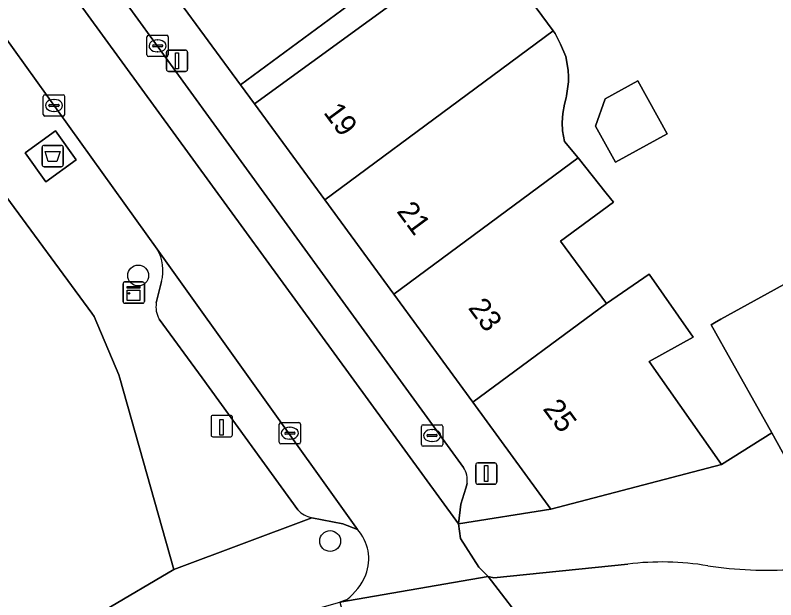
# Model space of a CAD drawing. Extents: x 161798 to 162385, y 382315 to 382833.
# Drawn here: x 162012.08 to 162047.7, y 382382.05 to 382409.46 of the extents above; entities that cross this region are included whole.
import ezdxf

# ---------------------------------------------------------------- set-up
doc = ezdxf.new("R2010")
doc.units = 0
for name, color, linetype in [('IMGEO_Afval_apart_plaats', 7, 'Continuous'), ('IMGEO_Boom', 7, 'Continuous'), ('IMGEO_Erf', 7, 'Continuous'), ('IMGEO_Fietspad_open', 7, 'Continuous'), ('IMGEO_Kast', 7, 'Continuous'), ('IMGEO_Kolk', 7, 'Continuous'), ('IMGEO_Laadpaal', 7, 'Continuous'), ('IMGEO_Lichtmast', 7, 'Continuous'), ('IMGEO_Pand', 7, 'Continuous'), ('IMGEO_Pand_nummerreeks', 7, 'Continuous'), ('IMGEO_Parkeervlak_open', 7, 'Continuous'), ('IMGEO_Rijbaan_lokaal_gesloten', 7, 'Continuous'), ('IMGEO_Rijbaan_lokaal_open', 7, 'Continuous'), ('IMGEO_Voetpad_gesloten', 7, 'Continuous'), ('IMGEO_Voetpad_open', 7, 'Continuous')]:
    doc.layers.add(name, color=color, linetype=linetype)

msp = doc.modelspace()

# ---------------------------------------------------------------- linework, layer by layer
at = {"layer": 'IMGEO_Afval_apart_plaats'}
for p, q in [((162013.335, 382402.456), (162013.335, 382403.256)), ((162013.335, 382403.256), (162013.335, 382402.456)), ((162013.435, 382403.356), (162014.225, 382403.356)), ((162014.225, 382403.356), (162013.435, 382403.356)), ((162014.325, 382403.256), (162014.325, 382402.456)), ((162014.325, 382402.456), (162014.325, 382403.256)), ((162014.225, 382402.356), (162013.435, 382402.356)), ((162013.435, 382402.356), (162014.225, 382402.356))]:
    msp.add_line(p, q, dxfattribs=at)
msp.add_lwpolyline([(162013.478, 382403.07), (162014.182, 382403.07), (162014.033, 382402.6), (162013.627, 382402.6), (162013.478, 382403.07)], dxfattribs=at)
for centre, start, end in [((162013.435, 382403.256), 90, 180), ((162013.435, 382403.256), 90, 180), ((162014.225, 382403.256), 0, 90), ((162014.225, 382403.256), 360, 90), ((162013.435, 382402.456), 180, 270), ((162013.435, 382402.456), 180, 270), ((162014.225, 382402.456), 270, 0), ((162014.225, 382402.456), 270, 0)]:
    msp.add_arc(centre, 0.1, start, end, dxfattribs=at)
at = {"layer": 'IMGEO_Boom'}
for centre in [(162017.836, 382397.254), (162026.826, 382384.808)]:
    msp.add_circle(centre, 0.489, dxfattribs=at)
at = {"layer": 'IMGEO_Erf'}
for points in [[(162033.311, 382414.087), (162022.628, 382406.187), (162023.288, 382405.3), (162034.023, 382413.125)], [(162035.94, 382410.533), (162037.275, 382408.724), (162037.365, 382408.601), (162037.619, 382408.106), (162037.863, 382407.521), (162037.979, 382406.887), (162037.982, 382406.573), (162037.984, 382406.331), (162037.894, 382405.679), (162037.872, 382405.582), (162037.802, 382405.282), (162037.726, 382404.852), (162037.698, 382404.423), (162037.701, 382404.042), (162037.801, 382403.535), (162038.444, 382402.777), (162039.754, 382401.12), (162040.089, 382400.696), (162037.607, 382398.861), (162039.763, 382395.945), (162041.759, 382397.315), (162043.834, 382394.36), (162041.77, 382393.217), (162045.159, 382388.391), (162047.51, 382389.884), (162045.251, 382393.911), (162045.115, 382394.154), (162044.67, 382394.948), (162044.823, 382395.032), (162045.13, 382395.203), (162050.256, 382398.043)]]:
    msp.add_lwpolyline(points, dxfattribs=at)
msp.add_lwpolyline([(162042.606, 382403.901), (162040.188, 382402.561), (162039.252, 382404.249), (162039.712, 382405.536), (162041.233, 382406.379)], close=True, dxfattribs=at)
at = {"layer": 'IMGEO_Fietspad_open'}
msp.add_lwpolyline([(162040.773, 382383.73), (162034.494, 382383.089), (162034.232, 382383.139), (162036.149, 382380.646), (162036.87, 382379.709)], dxfattribs=at)
for centre, radius, start, end in [((162042.359, 382370.687), 13.139, 80.5822, 96.9337), ((162047.361, 382402.946), 19.506, 261.594, 273.4107)]:
    msp.add_arc(centre, radius, start, end, dxfattribs=at)
at = {"layer": 'IMGEO_Kast'}
for p, q in [((162017.125, 382396.028), (162017.125, 382396.869)), ((162017.125, 382396.869), (162017.125, 382396.028)), ((162017.2, 382396.953), (162018.041, 382396.953)), ((162018.041, 382396.953), (162017.2, 382396.953)), ((162018.125, 382396.878), (162018.125, 382396.037)), ((162018.125, 382396.037), (162018.125, 382396.878)), ((162018.05, 382395.953), (162017.209, 382395.953)), ((162017.209, 382395.953), (162018.05, 382395.953))]:
    msp.add_line(p, q, dxfattribs=at)
for points in [[(162017.32, 382396.743), (162017.92, 382396.743), (162017.92, 382396.658), (162017.32, 382396.658), (162017.32, 382396.743)], [(162017.32, 382396.568), (162017.92, 382396.568), (162017.92, 382396.079), (162017.32, 382396.079), (162017.32, 382396.568)]]:
    msp.add_lwpolyline(points, dxfattribs=at)
msp.add_circle((162017.404, 382396.417), 0.0377, dxfattribs=at)
for centre, start, end in [((162017.203, 382396.875), 92.4484, 184.2845), ((162017.203, 382396.875), 92.4484, 184.2845), ((162018.047, 382396.875), 2.4484, 94.2845), ((162018.047, 382396.875), 2.4484, 94.2845), ((162017.203, 382396.031), 182.4484, 274.2845), ((162017.203, 382396.031), 182.4484, 274.2845), ((162018.047, 382396.031), 272.4484, 4.2845), ((162018.047, 382396.031), 272.4484, 4.2845)]:
    msp.add_arc(centre, 0.0779, start, end, dxfattribs=at)
at = {"layer": 'IMGEO_Kolk'}
for p, q in [((162018.245, 382407.593), (162018.245, 382408.445)), ((162018.32, 382408.519), (162019.172, 382408.519)), ((162018.733, 382408.299), (162018.758, 382408.299)), ((162019.246, 382408.445), (162019.246, 382407.593)), ((162018.504, 382408.013), (162018.504, 382408.025)), ((162018.942, 382407.976), (162018.544, 382407.976)), ((162018.547, 382408.062), (162018.945, 382408.062)), ((162018.988, 382408.025), (162018.988, 382408.013)), ((162018.756, 382407.739), (162018.731, 382407.739)), ((162019.172, 382407.519), (162018.32, 382407.519)), ((162013.391, 382404.8), (162013.391, 382405.652)), ((162013.466, 382405.726), (162014.318, 382405.726)), ((162013.879, 382405.506), (162013.904, 382405.506)), ((162014.392, 382405.652), (162014.392, 382404.8)), ((162013.65, 382405.22), (162013.65, 382405.232)), ((162014.088, 382405.183), (162013.69, 382405.183)), ((162013.693, 382405.269), (162014.091, 382405.269)), ((162014.134, 382405.232), (162014.134, 382405.22)), ((162014.318, 382404.726), (162013.466, 382404.726)), ((162013.902, 382404.946), (162013.877, 382404.946)), ((162024.439, 382389.437), (162024.439, 382390.289)), ((162024.514, 382390.363), (162025.366, 382390.363)), ((162024.927, 382390.143), (162024.952, 382390.143)), ((162025.44, 382390.289), (162025.44, 382389.437)), ((162031.1, 382389.329), (162031.1, 382390.181)), ((162031.175, 382390.255), (162032.027, 382390.255)), ((162032.101, 382390.181), (162032.101, 382389.329)), ((162024.698, 382389.857), (162024.698, 382389.869)), ((162025.136, 382389.82), (162024.738, 382389.82)), ((162024.741, 382389.906), (162025.139, 382389.906)), ((162025.182, 382389.869), (162025.182, 382389.857)), ((162031.359, 382389.749), (162031.359, 382389.761)), ((162031.402, 382389.798), (162031.8, 382389.798)), ((162031.588, 382390.035), (162031.613, 382390.035)), ((162031.843, 382389.761), (162031.843, 382389.749)), ((162025.366, 382389.363), (162024.514, 382389.363)), ((162024.95, 382389.583), (162024.925, 382389.583)), ((162031.797, 382389.712), (162031.399, 382389.712)), ((162031.611, 382389.475), (162031.586, 382389.475)), ((162032.027, 382389.255), (162031.175, 382389.255))]:
    msp.add_line(p, q, dxfattribs=at)
for points in [[(162018.245, 382407.593), (162018.245, 382408.445)], [(162018.32, 382408.519), (162019.172, 382408.519)], [(162019.246, 382408.445), (162019.246, 382407.593)], [(162019.172, 382407.519), (162018.32, 382407.519)], [(162013.391, 382404.8), (162013.391, 382405.652)], [(162013.466, 382405.726), (162014.318, 382405.726)], [(162014.392, 382405.652), (162014.392, 382404.8)], [(162014.318, 382404.726), (162013.466, 382404.726)], [(162024.439, 382389.437), (162024.439, 382390.289)], [(162024.514, 382390.363), (162025.366, 382390.363)], [(162025.44, 382390.289), (162025.44, 382389.437)], [(162031.1, 382389.329), (162031.1, 382390.181)], [(162031.175, 382390.255), (162032.027, 382390.255)], [(162032.101, 382390.181), (162032.101, 382389.329)], [(162025.366, 382389.363), (162024.514, 382389.363)], [(162032.027, 382389.255), (162031.175, 382389.255)]]:
    msp.add_lwpolyline(points, dxfattribs=at)
for centre, radius, start, end in [((162018.322, 382408.443), 0.0765, 91.552, 178.448), ((162018.322, 382408.443), 0.0765, 91.552, 178.448), ((162019.17, 382408.443), 0.0765, 1.552, 88.448), ((162019.17, 382408.443), 0.0765, 1.552, 88.448), ((162018.544, 382408.022), 0.0403, 85.8775, 175.7526), ((162018.541, 382408.012), 0.0366, 178.938, 274.7102), ((162018.945, 382408.019), 0.043, 264.8664, 352.4533), ((162018.949, 382408.024), 0.0386, 1.7309, 96.639), ((162018.322, 382407.595), 0.0765, 181.552, 268.448), ((162018.322, 382407.595), 0.0765, 181.552, 268.448), ((162019.17, 382407.595), 0.0765, 271.552, 358.448), ((162019.17, 382407.595), 0.0765, 271.552, 358.448), ((162013.468, 382405.65), 0.0765, 91.552, 178.448), ((162013.468, 382405.65), 0.0765, 91.552, 178.448), ((162014.316, 382405.65), 0.0765, 1.552, 88.448), ((162014.316, 382405.65), 0.0765, 1.552, 88.448), ((162013.69, 382405.229), 0.0403, 85.8775, 175.7526), ((162013.687, 382405.219), 0.0366, 178.938, 274.7102), ((162014.091, 382405.226), 0.043, 264.8664, 352.4533), ((162014.095, 382405.231), 0.0386, 1.7309, 96.639), ((162013.468, 382404.802), 0.0765, 181.552, 268.448), ((162013.468, 382404.802), 0.0765, 181.552, 268.448), ((162014.316, 382404.802), 0.0765, 271.552, 358.448), ((162014.316, 382404.802), 0.0765, 271.552, 358.448), ((162024.516, 382390.287), 0.0765, 91.552, 178.448), ((162024.516, 382390.287), 0.0765, 91.552, 178.448), ((162025.364, 382390.287), 0.0765, 1.552, 88.448), ((162025.364, 382390.287), 0.0765, 1.552, 88.448), ((162031.177, 382390.179), 0.0765, 91.552, 178.448), ((162031.177, 382390.179), 0.0765, 91.552, 178.448), ((162032.025, 382390.179), 0.0765, 1.552, 88.448), ((162032.025, 382390.179), 0.0765, 1.552, 88.448), ((162024.738, 382389.866), 0.0403, 85.8775, 175.7526), ((162024.735, 382389.856), 0.0366, 178.938, 274.7102), ((162025.139, 382389.863), 0.043, 264.8664, 352.4533), ((162025.143, 382389.868), 0.0386, 1.7309, 96.639), ((162031.399, 382389.758), 0.0403, 85.8775, 175.7526), ((162031.396, 382389.748), 0.0366, 178.938, 274.7102), ((162031.8, 382389.755), 0.043, 264.8664, 352.4533), ((162031.804, 382389.76), 0.0386, 1.7309, 96.639), ((162024.516, 382389.439), 0.0765, 181.552, 268.448), ((162024.516, 382389.439), 0.0765, 181.552, 268.448), ((162025.364, 382389.439), 0.0765, 271.552, 358.448), ((162025.364, 382389.439), 0.0765, 271.552, 358.448), ((162031.177, 382389.331), 0.0765, 181.552, 268.448), ((162031.177, 382389.331), 0.0765, 181.552, 268.448), ((162032.025, 382389.331), 0.0765, 271.552, 358.448), ((162032.025, 382389.331), 0.0765, 271.552, 358.448)]:
    msp.add_arc(centre, radius, start, end, dxfattribs=at)
for centre, major_axis, ratio, start_param, end_param in [((162018.732, 382408.019), (-0.387, 0.002), 0.722429, 4.712389, 7.853982), ((162018.757, 382408.019), (-0.39, 0.002), 0.717154, 1.570796, 4.712389), ((162013.878, 382405.226), (-0.387, 0.002), 0.722429, 4.712389, 7.853982), ((162013.903, 382405.226), (-0.39, 0.002), 0.717154, 1.570796, 4.712389), ((162024.926, 382389.863), (-0.387, 0.002), 0.722429, 4.712389, 7.853982), ((162024.951, 382389.863), (-0.39, 0.002), 0.717154, 1.570796, 4.712389), ((162031.587, 382389.755), (-0.387, 0.002), 0.722429, 4.712389, 7.853982), ((162031.612, 382389.755), (-0.39, 0.002), 0.717154, 1.570796, 4.712389)]:
    msp.add_ellipse(centre, major_axis=major_axis, ratio=ratio, start_param=start_param, end_param=end_param, dxfattribs=at)
at = {"layer": 'IMGEO_Laadpaal'}
for p, q in [((162021.248, 382390.614), (162021.248, 382389.773)), ((162021.248, 382390.614), (162021.248, 382389.773)), ((162022.164, 382390.698), (162021.323, 382390.698)), ((162022.164, 382390.698), (162021.323, 382390.698)), ((162022.248, 382389.782), (162022.248, 382390.623)), ((162022.248, 382389.782), (162022.248, 382390.623)), ((162021.332, 382389.698), (162022.173, 382389.698)), ((162021.332, 382389.698), (162022.173, 382389.698))]:
    msp.add_line(p, q, dxfattribs=at)
msp.add_lwpolyline([(162021.663, 382390.511), (162021.823, 382390.511), (162021.823, 382389.778), (162021.663, 382389.778), (162021.663, 382390.511)], dxfattribs=at)
for centre, start, end in [((162021.326, 382390.62), 92.4484, 184.2845), ((162021.326, 382390.62), 92.4484, 184.2845), ((162022.17, 382390.62), 2.4484, 94.2845), ((162022.17, 382390.62), 2.4484, 94.2845), ((162021.326, 382389.776), 182.4484, 274.2845), ((162021.326, 382389.776), 182.4484, 274.2845), ((162022.17, 382389.776), 272.4484, 4.2845), ((162022.17, 382389.776), 272.4484, 4.2845)]:
    msp.add_arc(centre, 0.0779, start, end, dxfattribs=at)
at = {"layer": 'IMGEO_Lichtmast'}
for p, q in [((162019.158, 382406.92), (162019.158, 382407.72)), ((162019.158, 382407.72), (162019.158, 382406.92)), ((162019.258, 382407.82), (162020.048, 382407.82)), ((162020.048, 382407.82), (162019.258, 382407.82)), ((162020.148, 382407.72), (162020.148, 382406.92)), ((162020.148, 382406.92), (162020.148, 382407.72)), ((162020.048, 382406.82), (162019.258, 382406.82)), ((162019.258, 382406.82), (162020.048, 382406.82)), ((162033.641, 382387.569), (162033.641, 382388.369)), ((162033.641, 382388.369), (162033.641, 382387.569)), ((162033.741, 382388.469), (162034.531, 382388.469)), ((162034.531, 382388.469), (162033.741, 382388.469)), ((162034.631, 382388.369), (162034.631, 382387.569)), ((162034.631, 382387.569), (162034.631, 382388.369)), ((162034.531, 382387.469), (162033.741, 382387.469)), ((162033.741, 382387.469), (162034.531, 382387.469))]:
    msp.add_line(p, q, dxfattribs=at)
for points in [[(162019.578, 382407.695), (162019.728, 382407.695), (162019.728, 382406.945), (162019.578, 382406.945), (162019.578, 382407.695)], [(162034.061, 382388.344), (162034.211, 382388.344), (162034.211, 382387.594), (162034.061, 382387.594), (162034.061, 382388.344)]]:
    msp.add_lwpolyline(points, dxfattribs=at)
for centre, start, end in [((162019.258, 382407.72), 90, 180), ((162019.258, 382407.72), 90, 180), ((162020.048, 382407.72), 0, 90), ((162020.048, 382407.72), 360, 90), ((162019.258, 382406.92), 180, 270), ((162019.258, 382406.92), 180, 270), ((162020.048, 382406.92), 270, 0), ((162020.048, 382406.92), 270, 0), ((162033.741, 382388.369), 90, 180), ((162033.741, 382388.369), 90, 180), ((162034.531, 382388.369), 0, 90), ((162034.531, 382388.369), 360, 90), ((162033.741, 382387.569), 180, 270), ((162033.741, 382387.569), 180, 270), ((162034.531, 382387.569), 270, 0), ((162034.531, 382387.569), 270, 0)]:
    msp.add_arc(centre, 0.1, start, end, dxfattribs=at)
at = {"layer": 'IMGEO_Pand'}
for points in [[(162028.892, 382420.064), (162029.989, 382420.875), (162029.76, 382421.198), (162027.154, 382424.872), (162022.598, 382421.64), (162025.311, 382417.648), (162018.079, 382412.392), (162022.628, 382406.187), (162033.311, 382414.087)], [(162037.275, 382408.724), (162035.94, 382410.533), (162034.023, 382413.125), (162023.288, 382405.3), (162026.571, 382400.806), (162033.241, 382405.74)], [(162038.444, 382402.777), (162037.801, 382403.535), (162037.701, 382404.042), (162037.698, 382404.423), (162037.726, 382404.852), (162037.802, 382405.282), (162037.872, 382405.582), (162037.894, 382405.679), (162037.984, 382406.331), (162037.982, 382406.573), (162037.979, 382406.887), (162037.863, 382407.521), (162037.619, 382408.106), (162037.365, 382408.601), (162037.275, 382408.724), (162033.241, 382405.74), (162026.571, 382400.806), (162029.806, 382396.378)], [(162039.252, 382404.249), (162040.188, 382402.561), (162042.606, 382403.901), (162041.233, 382406.379), (162039.712, 382405.536)], [(162038.444, 382402.777), (162029.806, 382396.378), (162033.504, 382391.316), (162039.763, 382395.945), (162037.607, 382398.861), (162040.089, 382400.696), (162039.754, 382401.12)], [(161992.986, 382387.688), (161996.279, 382375.983), (162000, 382377.033), (162005.41, 382378.559), (162009.526, 382379.708), (162009.093, 382381.268), (162011.466, 382381.97), (162011.964, 382380.39), (162012.37, 382380.501), (162016.275, 382381.566), (162019.512, 382383.48), (162016.974, 382392.447), (162016.93, 382392.603), (162015.773, 382395.333), (162015.66, 382395.487), (162011.459, 382401.201), (162002.027, 382394.301)], [(162050.256, 382398.043), (162045.13, 382395.203), (162044.823, 382395.032), (162044.67, 382394.948), (162045.115, 382394.154), (162045.251, 382393.911), (162047.51, 382389.884), (162049.503, 382386.257), (162055.054, 382389.385), (162051.941, 382395.003), (162051.601, 382395.616), (162050.944, 382396.801), (162050.426, 382397.737)], [(162033.504, 382391.316), (162037.166, 382386.303), (162045.159, 382388.391), (162041.77, 382393.217), (162043.834, 382394.36), (162041.759, 382397.315), (162039.763, 382395.945)]]:
    msp.add_lwpolyline(points, close=True, dxfattribs=at)
at = {"layer": 'IMGEO_Parkeervlak_open'}
for points in [[(162013.778, 382411.818), (162032.83, 382385.614), (162032.951, 382386.532), (162033.178, 382387.292), (162033.24, 382387.513)], [(162033.065, 382388.261), (162027.294, 382396.215), (162016.872, 382410.591)], [(162025.97, 382385.896), (162027.424, 382385.612), (162028.106, 382385.351), (162018.806, 382398.381), (162018.719, 382398.49)], [(162018.925, 382396.969), (162018.685, 382395.969)], [(162018.82, 382395.215), (162020.829, 382392.465), (162025.317, 382386.264)]]:
    msp.add_lwpolyline(points, dxfattribs=at)
for centre, radius, start, end in [((162017.071, 382397.492), 1.927, 344.2377, 31.1884), ((162019.772, 382395.774), 1.104, 169.8534, 210.4485), ((162032.197, 382387.664), 1.053, 351.7844, 34.5514), ((162026.253, 382387.162), 1.297, 223.8037, 257.3892)]:
    msp.add_arc(centre, radius, start, end, dxfattribs=at)
at = {"layer": 'IMGEO_Rijbaan_lokaal_gesloten'}
msp.add_lwpolyline([(162034.232, 382383.139), (162027.279, 382381.946), (162028.075, 382379.021), (162028.34, 382379.074), (162036.149, 382380.646)], close=True, dxfattribs=at)
at = {"layer": 'IMGEO_Rijbaan_lokaal_open'}
for points in [[(162013.778, 382411.818), (162012.33, 382413.906), (162009.488, 382418.005), (162002.849, 382427.58), (161999.682, 382425.259), (162009.841, 382410.886), (162009.951, 382410.728), (162018.719, 382398.49), (162018.806, 382398.381), (162028.106, 382385.351)], [(162027.597, 382382.054), (162027.279, 382381.946), (162034.232, 382383.139), (162033.787, 382383.577), (162032.934, 382384.925), (162032.83, 382385.614), (162013.778, 382411.818)]]:
    msp.add_lwpolyline(points, dxfattribs=at)
for centre, radius, start, end in [((162026.578, 382383.974), 2.057, 338.5663, 42.0387), ((162025.835, 382384.333), 2.881, 307.7062, 337.3085)]:
    msp.add_arc(centre, radius, start, end, dxfattribs=at)
at = {"layer": 'IMGEO_Voetpad_gesloten'}
msp.add_lwpolyline([(162013.96, 382404.032), (162012.536, 382403.004), (162013.513, 382401.65), (162014.937, 382402.678)], close=True, dxfattribs=at)
at = {"layer": 'IMGEO_Voetpad_open'}
for points in [[(161938.715, 382497.147), (161939.523, 382495.623), (161943.046, 382494.363), (161946.327, 382489.811), (161950.356, 382484.334), (161950.42, 382484.381), (161954.726, 382478.543), (161983.404, 382439.272), (161998.059, 382419.476), (162001.282, 382415.062), (162005.738, 382408.96), (162006.916, 382407.381), (162011.459, 382401.201), (162015.66, 382395.487), (162015.773, 382395.333), (162016.93, 382392.603), (162016.974, 382392.447), (162019.512, 382383.48), (162025.97, 382385.896)], [(162033.24, 382387.513), (162033.178, 382387.292), (162032.951, 382386.532), (162032.83, 382385.614), (162037.166, 382386.303), (162033.504, 382391.316), (162029.806, 382396.378), (162026.571, 382400.806), (162023.288, 382405.3), (162022.628, 382406.187), (162018.079, 382412.392), (162015.189, 382416.324), (162012.934, 382419.392), (161994.413, 382444.586)], [(162109.488, 382437.342), (162106.77, 382433.488), (162104.135, 382429.722), (162100.754, 382425.307), (162095.959, 382419.044), (162091.944, 382413.801), (162094.009, 382411.037), (162089.697, 382408.648), (162075.201, 382400.616), (162067.892, 382396.566), (162062.234, 382393.427), (162060.979, 382392.723), (162055.054, 382389.385), (162049.503, 382386.257), (162047.51, 382389.884), (162045.159, 382388.391), (162037.166, 382386.303), (162032.83, 382385.614), (162032.934, 382384.925), (162033.787, 382383.577), (162034.232, 382383.139), (162034.494, 382383.089), (162040.773, 382383.73)], [(162018.719, 382398.49), (162009.951, 382410.728), (162009.841, 382410.886)], [(162016.872, 382410.591), (162027.294, 382396.215), (162033.065, 382388.261)], [(162018.685, 382395.969), (162018.925, 382396.969)], [(162025.317, 382386.264), (162020.829, 382392.465), (162018.82, 382395.215)], [(162028.106, 382385.351), (162027.424, 382385.612), (162025.97, 382385.896), (162019.512, 382383.48), (162016.275, 382381.566), (162012.37, 382380.501), (162011.964, 382380.39), (162011.466, 382381.97), (162009.093, 382381.268), (162009.526, 382379.708), (162005.41, 382378.559), (162000, 382377.033), (161996.279, 382375.983), (161994.682, 382375.533), (161994.893, 382374.764), (161992.051, 382373.452), (161991.705, 382374.693), (161979.826, 382371.342), (161980.039, 382370.575)], [(161963.411, 382364.051), (161981.294, 382369.045), (162000, 382374.274), (162016.836, 382378.994), (162027.279, 382381.946), (162027.597, 382382.054)]]:
    msp.add_lwpolyline(points, dxfattribs=at)
msp.add_lwpolyline([(162013.513, 382401.65), (162012.536, 382403.004), (162013.96, 382404.032), (162014.937, 382402.678)], close=True, dxfattribs=at)
for centre, radius, start, end in [((162017.071, 382397.492), 1.927, 344.2377, 31.1884), ((162019.772, 382395.774), 1.104, 169.8534, 210.4485), ((162032.197, 382387.664), 1.053, 351.7844, 34.5514), ((162026.253, 382387.162), 1.297, 223.8037, 257.3892), ((162026.578, 382383.974), 2.057, 338.5663, 42.0387), ((162042.359, 382370.687), 13.139, 80.5822, 96.9337), ((162047.361, 382402.946), 19.506, 261.594, 273.4107), ((162025.835, 382384.333), 2.881, 307.7062, 337.3085)]:
    msp.add_arc(centre, radius, start, end, dxfattribs=at)

# ---------------------------------------------------------------- texts
at = {"layer": 'IMGEO_Pand_nummerreeks'}
for s, rotation, p in [('19', 306.4857, (162026.483, 382404.894)), ('21', 306.4857, (162029.911, 382400.26)), ('23', 306.4857, (162033.258, 382395.733)), ('25', 306.483, (162036.757, 382391.003))]:
    msp.add_text(s, height=1, rotation=rotation, dxfattribs=at).set_placement(p)

doc.saveas('drawing.dxf')
